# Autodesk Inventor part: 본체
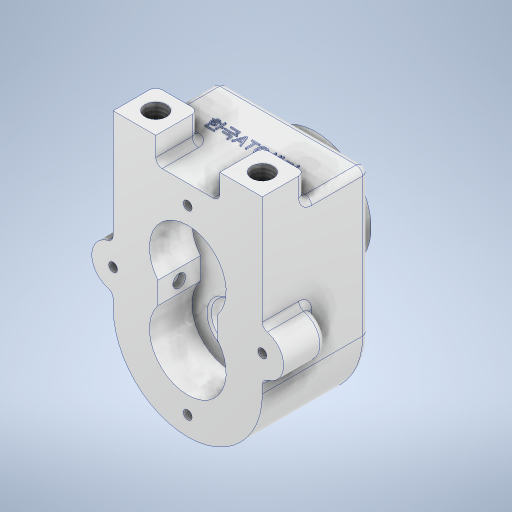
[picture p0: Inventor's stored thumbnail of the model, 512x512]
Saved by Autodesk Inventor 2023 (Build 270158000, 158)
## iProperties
Created: 2024-03
Part Number: 본체
Material: 알루미늄 6061
Document SubType Name: Modeling
Designer: asung
Density: 2.7 g/cm^3
Appearance: 알루미늄 - 평지
Author: asung
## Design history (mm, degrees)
sketch "스케치1"
  geometry: L1 (0, 0)-(0, 68); L2 (-35, 0)-(-35, 68); L3 (35, 0)-(35, 68); L4 (-35, 68)-(35, 68); C1 r 35 at (0, 0); 3 further points
  constraints: 8 end point, 2 parallel, 1 centre point, 1 coincident, 1 horizontal, 1 vertical
  dimensions: "d0" = 70 diameter of C1; "d1" = 68 distance of L1.start L1.end; "d2" = 35 distance between parallel lines of L1 L2; "d3" = 35 distance between parallel lines of L1 L3; "d4" = 68 distance from line of point (0, 0) L4; "d5" = 68 distance from line of L3.start L4; "d6" = 68 distance from line of L2.start L4
extrude "돌출1" new body sketch "스케치1" stored distance "d7" = 50; taper "d8" = 0 deg
sketch "스케치2"
  geometry: L1 (0, 50)-(0, 0) reference; L2 (70, 0)-(0, 0) reference; L3 (70, 0)-(70, 50) reference; L4 (0, 50)-(70, 50) reference; L5 (0, 0)-(20, 0); L6 (20, 0)-(20, 20); L7 (20, 20)-(0, 20); L8 (0, 20)-(0, 0); L9 (70, 0)-(50, 0); L10 (50, 0)-(50, 20); L11 (50, 20)-(70, 20); L12 (70, 20)-(70, 0); 5 further points
  constraints: 16 end point, 4 parallel, 2 horizontal, 2 perpendicular
  dimensions: "d9" = 20 distance of L7.end L6.end; "d10" = 20 distance of L6.end L5.end; "d11" = 20 distance of L10.end L11.end; "d12" = 20 distance of L9.end L10.end
extrude "돌출2" join sketch "스케치2" distance "d13" = 12; taper "d14" = 0 deg
fillet "모깎기1" dims "d15" = 3
fillet "모깎기2" dims "d16" = 3
sketch "스케치3"
  geometry: L1 (12, 68)-(-12, 68) reference; L2 (-15, 71)-(-15, 80) reference; L3 (-35, 80)-(-15, 80) reference; L4 (-35, 0)-(-35, 80) reference; L5 (35, 0)-(35, 80) reference; L6 (15, 80)-(35, 80) reference; L7 (15, 71)-(15, 80) reference; L8 (0, 68)-(0, 40); C1 r 10 at (-35, 16.5); C2 r 10 at (35, 16.5); A1 r 3 centre (-12, 71) between (-15, 71) and (-12, 68) reference; A2 r 35 centre (0, 0) between (-35, 0) and (35, 0) reference; A3 r 3 centre (12, 71) between (12, 68) and (15, 71) reference; 5 further points
  constraints: 2 centre point, 2 end point, 1 midpoint, 1 point on line, 1 symmetric about line, 1 vertical, 1 other
  dimensions: "d17" = 10 radius of C1; "d18" = 63.5 distance from line of C1.centre L3
extrude "돌출3" join sketch "스케치3" distance "d19" = 20; taper "d20" = 0 deg
fillet "모깎기3" dims "d21" = 3
fillet "모깎기4" dims "d22" = 3
sketch "스케치4"
  geometry: L1 (12, 68)-(-12, 68) reference; L2 (-15, 71)-(-15, 80) reference; L3 (-35, 80)-(-15, 80) reference; L4 (-35, 29.149)-(-35, 80) reference; L5 (-35, 0)-(-35, 3.851) reference; L6 (35, 0)-(35, 3.851) reference; L7 (35, 29.149)-(35, 80) reference; L8 (15, 80)-(35, 80) reference; L9 (15, 71)-(15, 80) reference; L10 (0, 33)-(0, 0); L11 (-14, 21.686)-(-14, 11.314); L12 (14, 21.686)-(14, 11.314); A1 r 3 centre (-12, 71) between (-15, 71) and (-12, 68) reference; A2 r 3 centre (-38, 29.149) between (-37.308, 26.23) and (-35, 29.149) reference; A3 r 10 centre (-35, 16.5) between (-37.308, 26.23) and (-37.308, 6.77) reference; A4 r 3 centre (-38, 3.851) between (-35, 3.851) and (-37.308, 6.77) reference; A5 r 35 centre (0, 0) between (-35, 0) and (35, 0) reference; A6 r 3 centre (38, 3.851) between (37.308, 6.77) and (35, 3.851) reference; A7 r 10 centre (35, 16.5) between (37.308, 6.77) and (37.308, 26.23) reference; A8 r 3 centre (38, 29.149) between (35, 29.149) and (37.308, 26.23) reference; A9 r 3 centre (12, 71) between (12, 68) and (15, 71) reference; A10 r 18 centre (0, 33) between (14, 21.686) and (-14, 21.686); A11 r 18 centre (0, 0) between (-14, 11.314) and (14, 11.314); 2 further points
  constraints: 6 end point, 4 point on circle, 2 centre point, 2 parallel, 1 midpoint, 1 vertical, 1 vertical alignment
  dimensions: "d23" = 36 diameter of A10; "d24" = 35 distance from line of L10.start L1; "d25" = 36 diameter of A11; "d26" = 33 distance of L10.end L10.start; "d27" = 14 distance between parallel lines of L10 L11; "d28" = 14 distance between parallel lines of L10 L12
extrude "돌출4" cut sketch "스케치4" distance "d29" = 20; taper "d30" = 0 deg
sketch "스케치5"
  geometry: L1 (35, 68)-(-35, 68) reference; L2 (-35, 68)-(-35, 0) reference; L3 (35, 0)-(35, 68) reference; C1 r 26 at (0, 33); A1 r 35 centre (0, 0) between (-35, 0) and (35, 0) reference; 2 further points
  constraints: 1 centre point, 1 midpoint, 1 vertical alignment
  dimensions: "d31" = 52 diameter of C1; "d32" = 35 distance from line of L1 C1.centre
extrude "돌출5" join sketch "스케치5" distance "d33" = 10; taper "d34" = 0 deg
sketch "스케치6"
  geometry: C1 r 26 at (0, 0) reference; C2 r 16 at (0, 0); A1 r 18 centre (0, 0) between (14, -11.314) and (-14, -11.314) reference; 1 further point
  constraints: 1 centre point, 1 coincident
  dimensions: "d35" = 32 diameter of C2
extrude "돌출6" join sketch "스케치6" distance "d36" = 4; taper "d37" = 0 deg
chamfer "모따기1" distance "d38" = 1; stored, may be unused: second distance "d39" = 2, angle "d40" = 45 deg
fillet "모깎기5" dims "d41" = 3
sketch "스케치7"
  geometry: A1 r 18 centre (0, 33) between (14, 21.686) and (-14, 21.686) reference; 2 further points
  constraints: 1 coincident
hole "구멍1" sketch "스케치7" at (0, 33) diameter "d42" = 15; stored, may be unused: countersink angle "d46" = 90 deg, drill point angle "d48" = 0 deg; dims "d43" = 8, "d44" = 20, "d45" = 10, "d47" = 30
sketch "스케치8"
  geometry: C1 r 15 at (0, 0) reference; 2 further points
  constraints: 1 coincident
hole "구멍2" sketch "스케치8" at (0, 0) diameter "d49" = 15; stored, may be unused: countersink angle "d53" = 90 deg, drill point angle "d55" = 0 deg; dims "d50" = 6, "d51" = 25, "d52" = 7.3, "d54" = 30
sketch "스케치9"
  geometry: A1 r 18 centre (0, 0) between (-14, 11.314) and (14, 11.314) reference; 2 further points
  constraints: 1 coincident
hole "구멍3" sketch "스케치9" at (0, 0) diameter "d59" = 20; stored, may be unused: countersink angle "d63" = 90 deg, drill point angle "d65" = 0 deg; dims "d60" = 6, "d61" = 25, "d62" = 7.3, "d64" = 10
chamfer "모따기3" distance "d66" = 1; stored, may be unused: second distance "d67" = 2, angle "d68" = 45 deg
sketch "스케치10"
  geometry: L1 (7, -35)-(7, -28) reference; L2 (17, -35)-(7, -35) reference; L3 (17, -38)-(17, -35) reference; L4 (18, -39)-(17, -38) reference; L5 (25.5, -31.7)-(20.5, -31.7) reference; L6 (25.5, -5)-(25.5, -31.7) reference; L7 (23, -5)-(25.5, -5) reference; L8 (43, 5)-(51, 5) reference; L9 (51, 5)-(51, 25) reference; L10 (51, 25)-(68, 25) reference; L11 (68, 25)-(68, -25) reference; L12 (68, -25)-(62, -25) reference; L13 (4, -25)-(-35, -25) reference; L14 (-35, -25)-(-35, 25) reference; L15 (-35, 25)-(-18, 25) reference; L16 (-18, 25)-(-18, 5) reference; L17 (-18, 5)-(-11, 5) reference; L18 (-11, 5)-(-10, 4) reference; L19 (-10, 4)-(-10, -5) reference; L20 (-10, -5)-(10, -5) reference; L21 (10, -5)-(10, 4) reference; L22 (10, 4)-(11, 5) reference; L23 (11, 5)-(23, 5) reference; L24 (40.5, -5)-(43, -5) reference; L25 (40.5, -31.7)-(40.5, -5) reference; L26 (45.5, -31.7)-(40.5, -31.7) reference; L27 (49, -38)-(48, -39) reference; L28 (49, -35)-(49, -38) reference; L29 (59, -35)-(49, -35) reference; L30 (59, -28)-(59, -35) reference; L31 (0, -25)-(0, 25) reference; L32 (10, -5)-(-10, -5) reference; L33 (7, -5)-(0, -9.041); L34 (23, 5)-(23, -5) reference; L35 (20.5, -31.7)-(20.5, -39) reference; L36 (20.5, -39)-(18, -39) reference; L37 (48, -39)-(45.5, -39) reference; L38 (45.5, -39)-(45.5, -31.7) reference; L39 (43, -5)-(43, 5) reference; A1 r 3 centre (4, -28) between (4, -25) and (7, -28) reference; A2 r 3 centre (62, -28) between (59, -28) and (62, -25) reference; 3 further points
  constraints: 2 end point, 2 point on line
  dimensions: "d70" = 7 distance from line of L31 L33.start; "d71" = 60 deg angle of L31 L33
revolve "회전1" sketch "스케치10" stored, may be unused: angle "d72" = 90 deg
sketch "스케치11"
  geometry: L1 (0, 0)-(0, -26); L2 (-14, 11.314)-(-14, 21.686) reference; L3 (14, 21.686)-(14, 11.314) reference; L4 (12, 68)-(-12, 68) reference; L5 (-15, 71)-(-15, 80) reference; L6 (-35, 80)-(-15, 80) reference; L7 (-35, 29.149)-(-35, 80) reference; L8 (-35, 0)-(-35, 3.851) reference; L9 (35, 0)-(35, 3.851) reference; L10 (35, 29.149)-(35, 80) reference; L11 (15, 80)-(35, 80) reference; L12 (15, 71)-(15, 80) reference; L13 (0, 33)-(0, 59); C1 r 29 at (0, 33) reference; A1 r 18 centre (0, 0) between (-14, 11.314) and (14, 11.314) reference; A2 r 18 centre (0, 33) between (14, 21.686) and (-14, 21.686) reference; A3 r 3 centre (-12, 71) between (-15, 71) and (-12, 68) reference; A4 r 3 centre (-38, 29.149) between (-37.308, 26.23) and (-35, 29.149) reference; A5 r 10 centre (-35, 16.5) between (-37.308, 26.23) and (-37.308, 6.77) reference; A6 r 3 centre (-38, 3.851) between (-35, 3.851) and (-37.308, 6.77) reference; A7 r 35 centre (0, 0) between (-35, 0) and (35, 0) reference; A8 r 3 centre (38, 3.851) between (37.308, 6.77) and (35, 3.851) reference; A9 r 10 centre (35, 16.5) between (37.308, 6.77) and (37.308, 26.23) reference; A10 r 3 centre (38, 29.149) between (35, 29.149) and (37.308, 26.23) reference; A11 r 3 centre (12, 71) between (12, 68) and (15, 71) reference; 4 further points
  constraints: 4 coincident, 4 end point, 2 vertical
  dimensions: "d73" = 26 distance of L1.start L1.end; "d74" = 26 distance of L13.start L13.end
hole "구멍4" sketch "스케치11" at (0, -26), (35, 16.5), (-35, 16.5), (0, 59) diameter "d75" = 4.134; stored, may be unused: countersink angle "d79" = 90 deg, drill point angle "d81" = 118 deg; dims "d76" = 10, "d77" = 4, "d78" = 2, "d80" = 12
sketch "스케치12" dims "d82" = 42
  geometry: C1 r 26 at (0, 0) reference; C2 r 7.5 at (0, 0) reference; 3 further points
  constraints: 1 coincident, 1 vertical alignment, 2 other
hole "구멍5" sketch "스케치12" at (0, 21) diameter "d83" = 3.242; stored, may be unused: countersink angle "d87" = 90 deg, drill point angle "d89" = 118 deg; dims "d84" = 8, "d85" = 4, "d86" = 2, "d88" = 10
sketch "스케치13"
  geometry: L1 (18, -39)-(17, -38) reference; L2 (17, -38)-(17, -35) reference; L3 (17, -35)-(13.621, -35) reference; L4 (13.621, -35)-(13.621, -25) reference; L5 (13.621, -25)-(12, -24.026) reference; L6 (12, -24.026)-(10.379, -25) reference; L7 (10.379, -25)-(10.379, -35) reference; L8 (10.379, -35)-(7, -35) reference; L9 (7, -35)-(7, -28) reference; L10 (4, -25)-(-35, -25) reference; L11 (-35, -25)-(-35, 25) reference; L12 (-35, 25)-(-28.067, 25) reference; L13 (-28.067, 25)-(-28.067, 13) reference; L14 (-28.067, 13)-(-26, 11.758) reference; L15 (-26, 11.758)-(-23.933, 13) reference; L16 (-23.933, 13)-(-23.933, 25) reference; L17 (-23.933, 25)-(-18, 25) reference; L18 (-18, 25)-(-18, 5) reference; L19 (-18, 5)-(-11, 5) reference; L20 (-11, 5)-(-10, 4) reference; L21 (-10, 4)-(-10, -5) reference; L22 (-10, -5)-(-7, -5) reference; L23 (-7, -5)-(0, -9.041) reference; L24 (0, -9.041)-(7, -5) reference; L25 (7, -5)-(10, -5) reference; L26 (10, -5)-(10, 4) reference; L27 (10, 4)-(11, 5) reference; L28 (11, 5)-(23, 5) reference; L29 (23, 5)-(23, -5) reference; L30 (23, -5)-(25.5, -5) reference; L31 (25.5, -5)-(25.5, -31.7) reference; L32 (25.5, -31.7)-(20.5, -31.7) reference; L33 (20.5, -31.7)-(20.5, -39) reference; L34 (20.5, -39)-(18, -39) reference; L35 (49, -38)-(48, -39) reference; L36 (48, -39)-(45.5, -39) reference; L37 (45.5, -39)-(45.5, -31.7) reference; L38 (45.5, -31.7)-(40.5, -31.7) reference; L39 (40.5, -31.7)-(40.5, -5) reference; L40 (40.5, -5)-(43, -5) reference; L41 (43, -5)-(43, 5) reference; L42 (43, 5)-(51, 5) reference; L43 (51, 5)-(51, 25) reference; L44 (51, 25)-(56.933, 25) reference; L45 (56.933, 25)-(56.933, 13) reference; L46 (56.933, 13)-(59, 11.758) reference; L47 (59, 11.758)-(61.067, 13) reference; L48 (61.067, 13)-(61.067, 25) reference; L49 (61.067, 25)-(68, 25) reference; L50 (68, 25)-(68, -25) reference; L51 (68, -25)-(62, -25) reference; L52 (59, -28)-(59, -35) reference; L53 (59, -35)-(55.621, -35) reference; L54 (55.621, -35)-(55.621, -25) reference; L55 (55.621, -25)-(54, -24.026) reference; L56 (54, -24.026)-(52.379, -25) reference; L57 (52.379, -25)-(52.379, -35) reference; L58 (52.379, -35)-(49, -35) reference; L59 (49, -35)-(49, -38) reference; L60 (45.5, -31.7)-(45.5, -39) reference; L61 (45.5, -38.3)-(45.904, -39); L62 (48, -39)-(18, -39) reference; L63 (33, -39)-(33, -30); A1 r 3 centre (4, -28) between (7, -28) and (4, -25) reference; A2 r 3 centre (62, -28) between (62, -25) and (59, -28) reference; 4 further points
  constraints: 4 end point, 2 midpoint, 2 point on line, 1 vertical
  dimensions: "d93" = 0.7 vertical distance of L61.start point (46.75, -39); "d94" = 30 deg angle of L37 L61
revolve "회전2" sketch "스케치13" stored, may be unused: angle "d95" = 90 deg
sketch "스케치15"
  geometry: L1 (17, 20)-(0, 20) reference; L2 (0, 20)-(0, 0) reference; L3 (0, 0)-(20, 0) reference; L4 (20, 0)-(20, 17) reference; L5 (50, 17)-(50, 0) reference; L6 (50, 0)-(70, 0) reference; L7 (70, 0)-(70, 20) reference; L8 (70, 20)-(53, 20) reference; A1 r 3 centre (17, 17) between (20, 17) and (17, 20) reference; A2 r 3 centre (53, 17) between (53, 20) and (50, 17) reference; 3 further points
  dimensions: "d103" = 10 distance from line of L1 point (10, 10); "d104" = 10 distance from line of L4 point (10, 10); "d105" = 10 distance from line of L8 point (60, 10); "d106" = 10 distance from line of L7 point (60, 10)
hole "구멍6" sketch "스케치15" at (10, 10), (60, 10) diameter "d107" = 10.106; stored, may be unused: countersink angle "d111" = 90 deg, drill point angle "d113" = 0 deg; dims "d108" = 14, "d109" = 4, "d110" = 2, "d112" = 16
node "작업 평면1"
sketch "스케치16"
  geometry: L1 (14, 11.314)-(14, 21.686) reference; L2 (-14, 21.686)-(-14, 11.314) reference; L3 (-12, 68)-(12, 68) reference; L4 (15, 71)-(15, 80) reference; L5 (15, 80)-(19.947, 80) reference; L6 (19.947, 80)-(19.947, 64) reference; L7 (19.947, 64)-(30.053, 64) reference; L8 (30.053, 64)-(30.053, 80) reference; L9 (30.053, 80)-(35, 80) reference; L10 (35, 80)-(35, 29.149) reference; L11 (35, 3.851)-(35, 0) reference; L12 (-35, 0)-(-35, 3.851) reference; L13 (-35, 29.149)-(-35, 80) reference; L14 (-35, 80)-(-30.053, 80) reference; L15 (-30.053, 80)-(-30.053, 64) reference; L16 (-30.053, 64)-(-19.947, 64) reference; L17 (-19.947, 64)-(-19.947, 80) reference; L18 (-19.947, 80)-(-15, 80) reference; L19 (-15, 80)-(-15, 71) reference; L20 (-19.947, 64)-(-30.053, 64) reference; L21 (-25, 64)-(-25, 24.5); L22 (-14, 11.314)-(-14, 21.686) reference; L23 (-14, 16.5)-(-17, 16.5); L24 (-35, 68)-(35, 68) reference; L25 (0, 68)-(0, 48.896); L26 (25, 64)-(25, 24.5); L27 (14, 16.5)-(17, 16.5); L28 (-28, 64)-(-28, 24.5); L29 (-17, 13.5)-(-14, 13.5); L30 (-25, 24.5)-(-28, 24.5); L31 (-17, 16.5)-(-17, 13.5); L32 (-14, 13.5)-(-14, 16.5); C1 r 2.067 at (-35, 16.5) reference; C2 r 2.067 at (0, -26) reference; C3 r 2.067 at (35, 16.5) reference; C4 r 2.067 at (0, 59) reference; A1 r 18 centre (0, 0) between (-14, 11.314) and (14, 11.314) reference; A2 r 18 centre (0, 33) between (14, 21.686) and (-14, 21.686) reference; A3 r 3 centre (-12, 71) between (-15, 71) and (-12, 68) reference; A4 r 3 centre (12, 71) between (12, 68) and (15, 71) reference; A5 r 3 centre (38, 29.149) between (35, 29.149) and (37.308, 26.23) reference; A6 r 10 centre (35, 16.5) between (37.308, 6.77) and (37.308, 26.23) reference; A7 r 3 centre (38, 3.851) between (37.308, 6.77) and (35, 3.851) reference; A8 r 35 centre (0, 0) between (-35, 0) and (35, 0) reference; A9 r 3 centre (-38, 3.851) between (-35, 3.851) and (-37.308, 6.77) reference; A10 r 10 centre (-35, 16.5) between (-37.308, 26.23) and (-37.308, 6.77) reference; A11 r 3 centre (-38, 29.149) between (-37.308, 26.23) and (-35, 29.149) reference; A12 r 8 centre (-17, 24.5) between (-25, 24.5) and (-17, 16.5); A13 r 8 centre (17, 24.5) between (17, 16.5) and (25, 24.5); A14 r 11 centre (-17, 24.5) between (-28, 24.5) and (-17, 13.5); 6 further points
  constraints: 20 end point, 6 point on circle, 5 symmetric about line, 3 centre point, 3 midpoint, 3 vertical, 2 perpendicular, 2 tangent, 1 collinear, 1 horizontal, 1 point on line, 3 other
  dimensions: "d114" = 63.5 distance of L21.start point (-25, 0.5); "d115" = 8 radius of A12; "d116" = 3 distance between parallel lines of L21 L28
  node "절단 모서리 투영4"
revolve "회전3" stored, may be unused: angle "d117" = 90 deg
revolve "회전4" stored, may be unused: angle "d118" = 90 deg
fillet "모깎기6" dims "d119" = 3
sketch "스케치17"
  geometry: L1 (-20, 23)-(-20, 47) reference; L2 (-6, 23)-(-20, 23) reference; L3 (0, 0)-(0, 17) reference; L4 (24, 0)-(0, 0) reference; L5 (24, 17)-(24, 0) reference; L6 (44, 23)-(30, 23) reference; L7 (44, 47)-(44, 23) reference; L8 (-20, 47)-(44, 47) reference; A1 r 6 centre (-6, 17) between (0, 17) and (-6, 23) reference; A2 r 6 centre (30, 17) between (30, 23) and (24, 17) reference; 2 further points
  constraints: 1 vertical alignment, 1 other
  dimensions: "d120" = 30 distance from line of point (12, 30) L4
feature "엠보싱1" sketch "스케치17" dims "d121" = 0.5, "d122" = 0
chamfer "모따기4" distance "d123" = 1; stored, may be unused: second distance "d124" = 2, angle "d125" = 45 deg
node "솔리드1"
pattern_circular "원형 패턴1" dims angle "d91" = 360 deg
mirror "미러1"
node "투영된 루프1"
node "투영된 루프2"
node "투영된 루프3"
node "투영된 루프4"
node "투영된 루프5"
node "투영된 루프8"
node "투영된 루프9"
node "투영된 루프10"
node "절단 모서리 투영1"
node "절단 모서리 투영2"
feature "A9D066F2-1C7D-4E18-AEED-F7BC21143FA4" dims "d42" = 15, "d43" = 8, "d44" = 20, "d45" = 10, "d46" = 90 deg, "d47" = 30, "d48" = 0
